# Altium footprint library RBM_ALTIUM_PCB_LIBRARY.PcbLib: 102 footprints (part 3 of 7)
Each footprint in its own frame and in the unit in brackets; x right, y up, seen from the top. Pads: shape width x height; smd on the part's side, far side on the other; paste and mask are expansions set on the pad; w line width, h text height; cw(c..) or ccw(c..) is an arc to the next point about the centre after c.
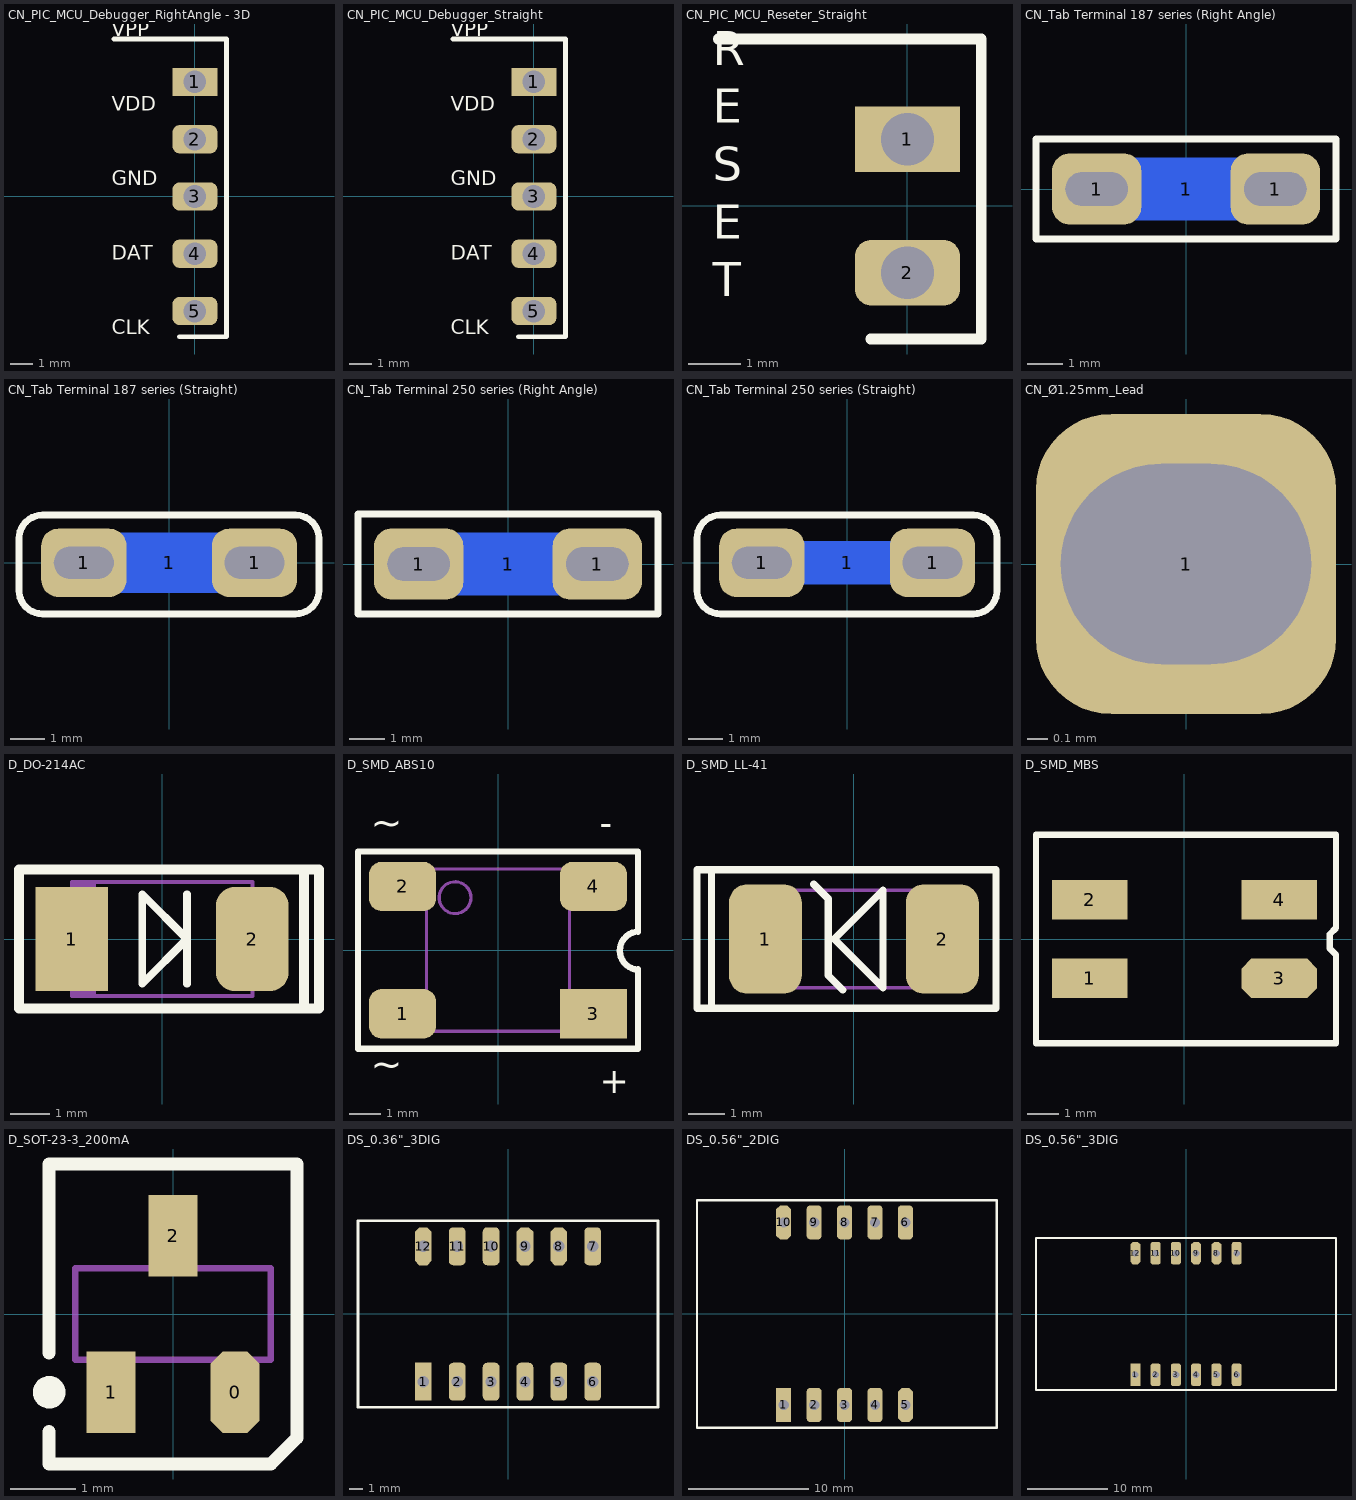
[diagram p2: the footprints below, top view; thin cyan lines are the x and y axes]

## CN_PIC_MCU_Debugger_RightAngle - 3D [mm] "2.54mmPitch, 5pins, StraightType, Male Connector"
pads (5):
  rect 2x1.25 hole 1: 1(0,5.08)
  rrect50% 2x1.25 hole 1: 2(0,2.54) 3(0,0) 4(0,-2.54) 5(0,-5.08)
Top Overlay:
  lines w0.203: -3.6,6.985 1.4,6.985 1.4,-6.22 -0.7,-6.22
  text "VPP /  /  / VDD /  /  / GND /  /  / DAT /  /  / CLK" at -3.7,-6.32 h1.1
Bottom Overlay:
  lines w0.203: -3.6,6.98 1.4,6.98 1.4,-6.225 -0.7,-6.225
  text "VPP /  /  / VDD /  /  / GND /  /  / DAT /  /  / CLK" at -1.3,-6.32 h1.1
3D body "5-Way 2.54mm Right Angle Male Header.STEP": height 2.51, standoff -3, extent -0.365,-6.32 9.765,6.38

## CN_PIC_MCU_Debugger_Straight [mm] "2.54mmPitch, 5pins, StraightType, Male Connector"
pads (5):
  rect 2x1.25 hole 1: 1(0,5.08)
  rrect50% 2x1.25 hole 1: 2(0,2.54) 3(0,0) 4(0,-2.54) 5(0,-5.08)
Top Overlay:
  lines w0.203: -3.6,6.985 1.4,6.985 1.4,-6.22 -0.7,-6.22
  text "VPP /  /  / VDD /  /  / GND /  /  / DAT /  /  / CLK" at -3.7,-6.32 h1.1
Bottom Overlay:
  lines w0.203: -3.6,6.98 1.4,6.98 1.4,-6.225 -0.7,-6.225
  text "VPP /  /  / VDD /  /  / GND /  /  / DAT /  /  / CLK" at -1.3,-6.32 h1.1
3D body "5Pins 2.54mm Male Header.STEP": height 8.54, standoff -3, extent -1.245,-6.35 1.245,6.35

## CN_PIC_MCU_Reseter_Straight [mm] "2.54mmPitch, 2pins, StraightType, Male Connector"
pads (2):
  rect 2x1.25 hole 1: 1(0,1.27)
  rrect50% 2x1.25 hole 1: 2(0,-1.27)
Top Overlay:
  lines w0.203: -3.6,3.175 1.4,3.175 1.4,-2.53 -0.7,-2.53
  text "R / E / S / E / T" at -3.7,-1.93 h1.1
Bottom Overlay:
  lines w0.203: -3.6,3.17 1.4,3.17 1.4,-2.53 -0.7,-2.53
  text "R / E / S / E / T" at -1.3,-1.93 h1.1
3D body "User Library-Header_Male_2Pin.STEP": height 8.54, standoff -3, extent -1.245,-2.54 1.245,2.54

## CN_Tab Terminal 187 series (Right Angle) [mm]
pads (3):
  rrect50% 2.5x2 hole 0.95 slot 1.75 at 0 deg: 1(-2.5,0) 1(2.5,0)
  rect 2.85x1.75 smd far side: 1(0,0)
Top Overlay:
  lines w0.2: -4.2,-1.397 4.2,-1.397 4.2,1.397 -4.2,1.397 -4.2,-1.397
3D body "4.8mm PCB Tab Terminal (Right Angle).stp": height 9.3, standoff -3.7, extent -3.3,-0.4 9.5,0.4

## CN_Tab Terminal 187 series (Straight) [mm]
pads (3):
  rrect50% 2.5x2 hole 0.95 slot 1.75 at 0 deg: 1(-2.5,0) 1(2.5,0)
  rect 2.85x1.75 smd far side: 1(0,0)
Top Overlay:
  lines w0.2: -4.4,-0.81 ccw(c-3.712,-0.81) -3.712,-1.498 3.7,-1.497 ccw(c3.7,-0.81) 4.388,-0.81 ; -4.4,-0.8 -4.4,0.712 ; -4.4,0.71 cw(c-3.712,0.71) -3.712,1.398 ; -3.712,1.397 3.7,1.397 ; 3.7,1.398 cw(c3.7,0.71) 4.388,0.71 ; 4.388,-0.812 4.388,0.7
3D body "4.8mm PCB Tab Terminal (Straight).stp": height 9, standoff -3.45, extent -3.962,-1.3 3.962,1.494

## CN_Tab Terminal 250 series (Right Angle) [mm]
pads (3):
  rrect50% 2.5x2 hole 0.95 slot 1.75 at 0 deg: 1(-2.5,0) 1(2.5,0)
  rect 2.85x1.75 smd far side: 1(0,0)
Top Overlay:
  lines w0.2: -4.2,-1.397 4.2,-1.397 4.2,1.397 -4.2,1.397 -4.2,-1.397
3D body "6.3mm PCB Tab Terminal (Right Angle).STEP": height 9.1, standoff -2.9, extent -4,-0.4 12.2,0.4

## CN_Tab Terminal 250 series (Straight) [mm]
pads (3):
  rrect50% 2.5x2 hole 0.95 slot 1.75 at 0 deg: 1(-2.5,0) 1(2.5,0)
  rect 2.85x1.25 smd far side: 1(0,0)
Top Overlay:
  lines w0.2: -4.4,-0.81 ccw(c-3.712,-0.81) -3.712,-1.498 3.7,-1.497 ccw(c3.7,-0.81) 4.388,-0.81 ; -4.4,-0.8 -4.4,0.712 ; -4.4,0.71 cw(c-3.712,0.71) -3.712,1.398 ; -3.712,1.397 3.7,1.397 ; 3.7,1.398 cw(c3.7,0.71) 4.388,0.71 ; 4.388,-0.812 4.388,0.7
3D body "6.3mm PCB Tab Terminal (Straight).stp": height 10.2, standoff -3.8, extent -4,-0.4 4,0.4

## CN_Ø1.25mm_Lead [mm] "Lead Wire"
pads (1):
  rrect50% 1.5x1.5 / inner rrect50% 1.5x1.5 / far side rrect50% 2.5x1.5 hole 1.25 slot 1 at 90 deg: 1(0,0)

## D_DO-214AC [mm] "RS1M; 1000V 1A 1.3V @ 1A 500ns SMA Diodes - Rectifiers - Fast Recovery RoHS"
height 2.44
pads (2):
  rect 1.85x2.65 smd: 1(-2.3,0)
  rrect50% 1.85x2.65 smd: 2(2.3,0)
Top Overlay:
  lines w0.2: 0.635,-1.143 0.635,1.143 ; -0.508,-1.143 -0.508,1.143 0.635,0 -0.508,-1.143
  lines w0.254: 3.619,-1.778 3.619,1.778 ; -3.65,-1.778 -3.65,1.778 4,1.778 4,-1.778 -3.65,-1.778
Mechanical 13:
  rectangle: -2.3,-1.45 -1.681,1.45
  lines w0.1: -2.3,-1.45 -2.3,1.45 2.3,1.45 2.3,-1.45 -2.3,-1.45
3D body "DIOM4327X24N.step": height 2.44, standoff 0, extent -2.52,-1.45 2.52,1.45

## D_SMD_ABS10 [mm]
pads (4):
  rrect50% 2.1x1.55 smd: 1(-3,-2) 2(-3,2) 4(3,2)
  rect 2.1x1.55 smd: 3(3,-2)
Top Overlay:
  lines w0.2: 4.299,-0.603 cw(c4.427,-0.017) 4.306,0.57 ; 4.4,-0.603 4.4,-3.1 -4.4,-3.1 -4.4,3.1 4.4,3.1 4.4,0.57
  text "~" at -4,3.3 h1.5
  text "+" at 3.2,-3.8 h0.8
  text "-" at 3.2,4.2 h0.8
  text "~" at -4,-4.3 h1.5
Mechanical 13:
  circle w0.1: c-1.35,1.65 r0.5
  lines w0.1: -2.25,-2.55 2.25,-2.55 2.25,2.55 -2.25,2.55 -2.25,-2.55
3D body "TSOP400P650X160-4N.step": height 1.6, standoff 0, extent -3.25,-2.55 3.25,2.55

## D_SMD_LL-41 [mm]
height 2.67
pads (2):
  rrect50% 2x3 smd: 1(-2.425,0) 2(2.425,0)
Top Overlay:
  lines w0.2: -3.9,-1.8 -3.9,1.8 ; -1.1,1.5 -0.7,1.1 -0.7,-1 -0.3,-1.4 ; -4.3,-1.9 3.9,-1.9 3.9,1.9 -4.3,1.9 -4.3,-1.9 ; -0.535,0 0.8,1.335 0.8,-1.335 -0.535,0
Mechanical 13:
  lines w0.1: -2.75,-1.335 -2.75,1.335 2.75,1.335 2.75,-1.335 -2.75,-1.335
3D body "ZD.step": height 2.46, standoff 0.01, extent -2.575,-1.227 2.575,1.228

## D_SMD_MBS [mm] "MB10S-10; MBS Bridge Rectifiers RoHS"
pads (4):
  rect 2.4x1.25 smd: 1(-3,-1.25) 2(-3,1.25) 4(3,1.25)
  oct 2.4x1.25 smd: 3(3,-1.25)
Top Overlay:
  lines w0.2: -4.7,-3.3 -4.7,3.3 4.8,3.3 4.8,0.35 4.6,0.15 4.6,-0.3 4.8,-0.5 4.8,-3.3 -4.7,-3.3
3D body "User Library-MB10F TMBS.step": height 1.61, standoff 0, extent -3.4,-2.45 3.4,2.45

## D_SOT-23-3_200mA [mm] "Diodes - General Purpose 100V 200mA 1.25V @ 200mA SOT-23(SOT-23-3) RoHS"
height 1.15
pads (3):
  oct 0.75x1.25 smd: 0(0.95,-1.2)
  rect 0.75x1.25 smd: 1(-0.95,-1.2) 2(0,1.2)
Top Overlay:
  circle w0.25: c-1.9,-1.2 r0.125
  lines w0.2: -1.9,-1.8 -1.9,-2.3 1.5,-2.3 1.9,-1.9 1.9,2.3 -1.9,2.3 -1.9,-0.6
Mechanical 13:
  lines w0.1: -1.5,-0.7 -1.5,0.7 1.5,0.7 1.5,-0.7 -1.5,-0.7
3D body "SOT95P245X115-3N.step": height 1.15, standoff 0, extent -1.5,-1.3 1.5,1.3

## DS_0.36"_3DIG [mm] "SLR0363DWC1BD"
pads (12):
  rect 1.25x2.85 hole 0.85: 1(-6.35,-5.08)
  rrect50% 1.25x2.85 hole 0.85: 2(-3.81,-5.08) 3(-1.27,-5.08) 4(1.27,-5.08) 5(3.81,-5.08) 6(6.35,-5.08) 7(6.35,5.08) 10(-1.27,5.08) 11(-3.81,5.08)
  oct 1.25x2.85 hole 0.85: 8(3.81,5.08) 9(1.27,5.08) 12(-6.35,5.08)
Top Overlay:
  lines w0.2: -11.25,-7 11.25,-7 11.25,7 -11.25,7 -11.25,-7
Bottom Overlay:
  text "D1" at -5.67,1.45 h1
  text "D2" at 2.13,1.45 h1
  text "D3" at 4.64,1.45 h1
  text "d" at -3.5,-2.25 h1
  text "dp" at -0.5,-2.25 h1
  text "e" at -6.1,-2.25 h1
  text "c" at 1.6,-2.25 h1
  text "g" at 4.1,-2.25 h1
  text "f" at -1.07,1.45 h1
  text "b" at 6.73,1.45 h1
  text "a" at -3.37,1.45 h1
3D body "User Library-atd-036ab.step": height 7.2, standoff -3.05, extent -11.3,-7.05 11.3,7.05

## DS_0.56"_2DIG [mm]
pads (10):
  rect 1.25x2.85 hole 0.85: 1(-5.08,-7.62)
  rrect50% 1.25x2.85 hole 0.85: 2(-2.54,-7.62) 3(0,-7.62) 4(2.54,-7.62) 6(5.08,7.62) 7(2.54,7.62) 8(0,7.62) 9(-2.54,7.62)
  oct 1.25x2.85 hole 0.85: 5(5.08,-7.62) 10(-5.08,7.62)
Top Overlay:
  lines w0.2: -12.319,-9.525 -12.319,9.475 12.7,9.475 12.7,-9.525 ; -12.28,-9.525 12.72,-9.525
Bottom Overlay:
  text "d" at -4.878,-4.833 h1
  text "dp" at -1.738,-4.9 h1
  text "e" at 0.201,-4.833 h1
  text "c" at 2.742,-4.833 h1
  text "g" at -2.24,4.3 h1
  text "f" at 0.301,4.167 h1
  text "b" at 5.38,4.167 h1
  text "a" at 2.9,4.167 h1
  text "D1" at -4.4,4.1 h1
  text "D2" at 5.8,-5 h1
3D body: height 7, standoff 1, extent -12.3,-9.313 12.719,9.61
3D body: height 7, standoff 1, extent -12.319,-9.525 12.7,9.398
3D body: height 3, standoff -3, extent -2.798,-7.879 -2.28,-7.36
3D body: height 3, standoff -3, extent -0.258,-7.879 0.26,-7.36
3D body: height 3, standoff -3, extent 2.282,-7.879 2.8,-7.36
3D body: height 3, standoff -3, extent 4.822,-7.879 5.34,-7.36
3D body: height 3, standoff -3, extent -5.338,-7.879 -4.82,-7.36
3D body: height 3, standoff -3, extent 4.822,7.361 5.34,7.88
3D body: height 3, standoff -3, extent 2.282,7.361 2.8,7.88
3D body: height 3, standoff -3, extent -0.258,7.361 0.26,7.88
3D body: height 3, standoff -3, extent -2.798,7.361 -2.28,7.88
3D body: height 3, standoff -3, extent -5.338,7.361 -4.82,7.88

## DS_0.56"_3DIG [mm]
pads (12):
  rect 1.25x2.85 hole 0.85: 1(-6.35,-7.62)
  rrect50% 1.25x2.85 hole 0.85: 2(-3.81,-7.62) 3(-1.27,-7.62) 4(1.27,-7.62) 5(3.81,-7.62) 6(6.35,-7.62) 7(6.35,7.62) 10(-1.27,7.62) 11(-3.81,7.62)
  oct 1.25x2.85 hole 0.85: 8(3.81,7.62) 9(1.27,7.62) 12(-6.35,7.62)
Top Overlay:
  lines w0.2: -18.796,-9.525 -18.796,9.525 18.796,9.525 18.796,-9.525 -18.796,-9.525
Bottom Overlay:
  text "D1" at -5.67,4.2 h1
  text "D2" at 2.13,4.2 h1
  text "D3" at 4.64,4.2 h1
  text "d" at -3.5,-4.8 h1
  text "dp" at -0.5,-4.7 h1
  text "e" at -6.1,-4.767 h1
  text "c" at 1.6,-4.7 h1
  text "g" at 4.1,-4.567 h1
  text "f" at -1.07,4.3 h1
  text "b" at 6.73,4.2 h1
  text "a" at -3.37,4.3 h1
3D body "User Library-5631_w_o_color_jam.step": height 8.1, standoff -5.5, extent -18.796,-9.525 18.804,9.475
